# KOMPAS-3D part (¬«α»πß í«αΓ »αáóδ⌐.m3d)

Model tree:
1. Эскиз:2
2. Операция выдавливания:1
     Расстояние 1 = 196.7; Расстояние 2 = 109.5
3. Смещенная плоскость:1
     Расстояние = 68.3
4. Эскиз:3
5. Операция выдавливания:2
     Расстояние 1 = 160; Расстояние 2 = 12.2
6. Эскиз:4
7. Вырезать элемент выдавливания:1
     Расстояние 1 = 300.7
8. Эскиз:6
9. Операция выдавливания:3
     Расстояние 1 = 89.3; Расстояние 2 = 12
10. Эскиз:50
11. Операция выдавливания:25
     Расстояние 1 = 2; Расстояние 2 = 2
12. Эскиз:52
13. Вырезать элемент выдавливания:22
     Расстояние 1 = 12.2
14. Эскиз:53
15. Вырезать элемент выдавливания:23
     Расстояние 1 = 12.2
16. Эскиз:54
17. Вырезать элемент выдавливания:24
     Расстояние 1 = 12.2
18. Эскиз:56
19. Вырезать элемент выдавливания:25
     Расстояние 1 = 0.7
20. Эскиз:62
21. Операция выдавливания:29
     Расстояние 1 = 160; Расстояние 2 = 12.2
22. Эскиз:63
23. Вырезать элемент выдавливания:30
     Расстояние 1 = 12.2
24. Эскиз:67
25. Вырезать элемент выдавливания:33
     Расстояние 1 = 12.2
26. Эскиз:73
27. Операция выдавливания:31
     Расстояние 1 = 196.7; Расстояние 2 = 9
28. Эскиз:74
29. Вырезать элемент выдавливания:39
     Расстояние 1 = 1.5
30. Эскиз:85
31. Вырезать элемент выдавливания:41
     Расстояние 1 = 11.6856
32. Эскиз:86
33. Вырезать элемент выдавливания:42
     Расстояние 2 = 0.514358; Расстояние 1 = 11.6856
34. Эскиз:88
35. Вырезать элемент выдавливания:44
     Расстояние 1 = 0.5
36. Эскиз:89
37. Вырезать элемент выдавливания:45
     Расстояние 1 = 8.87623
38. Эскиз:90
39. Вырезать элемент выдавливания:46
     Расстояние 1 = 11.6856
40. Вырезать элемент выдавливания:47
     Расстояние 1 = 12.2
41. Эскиз:92
42. Вырезать элемент выдавливания:48
     Расстояние 1 = 11.6856
43. Эскиз:93
44. Вырезать элемент выдавливания:49
     Расстояние 1 = 300.693
45. Скругление:1
     Радиус = 2
46. Скругление:2
     Радиус = 0.3
47. Скругление:3
     Радиус = 0.3
48. Скругление:4
     Радиус = 0.1
49. Скругление:5
     Радиус = 1
50. Скругление:6
     Радиус = 2
51. Скругление:7
     Радиус = 2
52. Скругление:8
     Радиус = 0.1
53. Скругление:9
     Радиус = 0.1
54. Скругление:10
     Радиус = 0.1
55. Зеркальный массив:1  (with: Операция выдавливания:1, Операция выдавливания:2, Вырезать элемент выдавливания:1, Операция выдавливания:3, Операция выдавливания:25, Вырезать элемент выдавливания:22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)  (labels: Экземпляр ( 1 ); Экземпляр ( 2 ))

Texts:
  корпус борт левый
  Сплав АЛ8  ГОСТ 1583-93
  stalker61
  Экземпляр ( 1 )
  Экземпляр ( 2 )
